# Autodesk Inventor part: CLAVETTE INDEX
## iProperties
Created: 2004-11
Part Number: CLAVETTE INDEX
Document SubType Name: Modeling
Designer: Bruno
Manufacturer: Standard
Standards Organization: Custom
Author: Bruno
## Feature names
1. Base1
